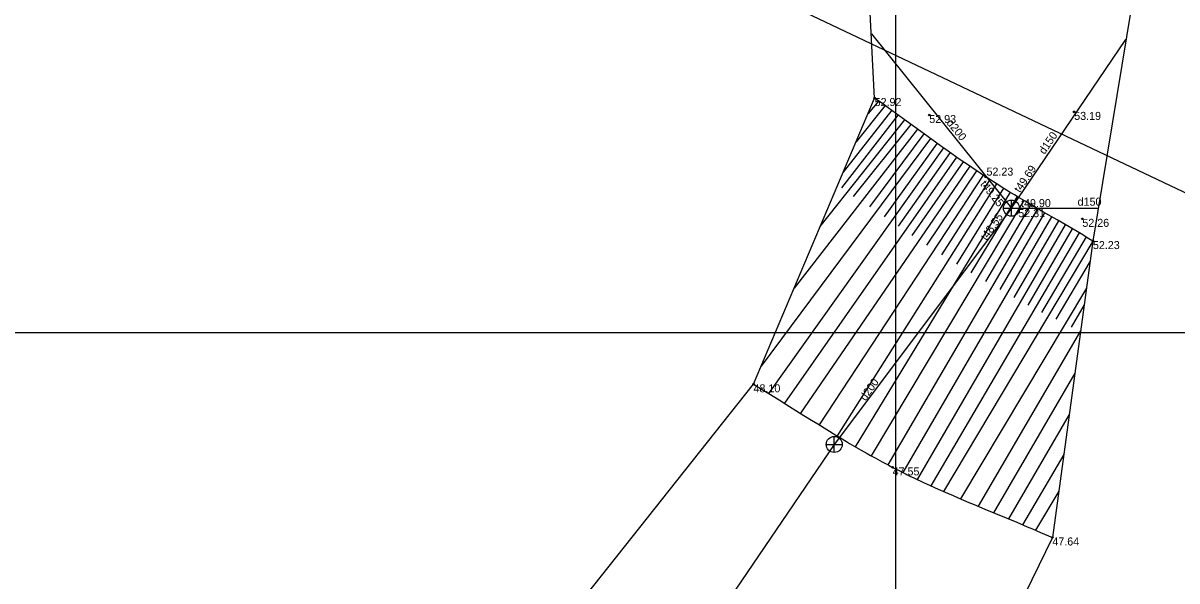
# Model space of a CAD drawing. Extents: x 561134 to 561329, y 413819 to 414116.
# Drawn here: x 561184.1 to 561256.1, y 413952.5 to 413987.3 of the extents above; entities that cross this region are included whole.
import ezdxf

# ---------------------------------------------------------------- set-up
doc = ezdxf.new("R2010")
doc.units = 0
for name, color, linetype in [('RAMI_PLAN_####_TKST_#', 7, 'Continuous'), ('RAMI_UZMR_####_####_#', 7, 'Continuous'), ('RELJ_AATZ_####_TKST_#', 7, 'Continuous'), ('RELJ_ELEM_####_####_#', 7, 'Continuous'), ('RELJ_NOGA_####_####_#', 7, 'Continuous'), ('RELJ_NOGL_####_####_#', 7, 'Continuous'), ('ROBZ_UZMR_####_####_#', 7, 'Continuous'), ('SKAN_ELEM_####_####_#', 7, 'Continuous'), ('SKAN_ELEM_PAST_TKST_#', 7, 'Continuous'), ('SKAN_VADP_PAST_####_#', 7, 'Continuous'), ('SKAN_VADP_PAST_TKST_#', 7, 'Continuous')]:
    doc.layers.add(name, color=color, linetype=linetype)

msp = doc.modelspace()

# ---------------------------------------------------------------- linework, layer by layer
at = {"layer": 'RAMI_PLAN_####_TKST_#'}
for p, q in [((561238.578, 413967.995), (561238.578, 414116.495)), ((561328.578, 413967.995), (561133.578, 413967.995)), ((561238.578, 413819.495), (561238.578, 413967.995))]:
    msp.add_line(p, q, dxfattribs=at)
at = {"layer": 'RAMI_UZMR_####_####_#'}
for points in [[(561188.512, 413892.082), (561185.041, 413910.753), (561191.104, 413917.736), (561189.205, 413920.568), (561187.984, 413924.22), (561187.954, 413928.121), (561192.417, 413932.029), (561202.582, 413934.262), (561206.983, 413936.681), (561215.453, 413945.229), (561216.519, 413946.905), (561218.27, 413950.393), (561229.69, 413964.77), (561237.253, 413982.653), (561235.655, 414013.737)], [(561254.18, 413993.826), (561250.885, 413973.719), (561248.352, 413955.204), (561242.331, 413942.835), (561241.508, 413940.241), (561240.647, 413938.452), (561234.45, 413929.795), (561214.305, 413914.287), (561206.991, 413896.237), (561188.512, 413892.082)]]:
    msp.add_lwpolyline(points, dxfattribs=at)
at = {"layer": 'RELJ_ELEM_####_####_#'}
for centre in [(561237.253, 413982.653), (561249.717, 413981.787), (561240.665, 413981.592), (561244.192, 413977.725), (561250.225, 413975.106), (561250.885, 413973.719), (561229.69, 413964.77), (561238.375, 413959.583), (561248.352, 413955.204)]:
    msp.add_circle(centre, 0.05, dxfattribs=at)
at = {"layer": 'RELJ_NOGA_####_####_#'}
for p, q in [((561237.508, 413982.471), (561236.844, 413981.686)), ((561238.319, 413981.887), (561235.292, 413978.016)), ((561237.914, 413982.18), (561236.094, 413979.912)), ((561233.858, 413974.624), (561239.128, 413981.298)), ((561235.209, 413977.042), (561238.724, 413981.593)), ((561235.938, 413976.5), (561239.532, 413981.004)), ((561239.936, 413980.71), (561232.23, 413970.775)), ((561236.949, 413975.863), (561240.34, 413980.415)), ((561240.745, 413980.122), (561230.169, 413965.903)), ((561241.556, 413979.537), (561230.624, 413964.204)), ((561241.15, 413979.829), (561237.837, 413975.236)), ((561242.372, 413978.959), (561231.622, 413963.588)), ((561241.964, 413979.248), (561238.712, 413974.642)), ((561243.195, 413978.391), (561232.627, 413962.96)), ((561242.783, 413978.674), (561239.582, 413974.056)), ((561243.609, 413978.111), (561240.487, 413973.458)), ((561244.026, 413977.834), (561233.781, 413962.24)), ((561244.445, 413977.561), (561241.422, 413972.856)), ((561244.866, 413977.292), (561234.905, 413961.55)), ((561245.716, 413976.765), (561236.038, 413960.874)), ((561245.29, 413977.027), (561242.356, 413972.275)), ((561246.572, 413976.248), (561237.035, 413960.304)), ((561246.143, 413976.505), (561243.26, 413971.73)), ((561247.002, 413975.994), (561244.17, 413971.199)), ((561247.433, 413975.74), (561238.07, 413959.742)), ((561248.297, 413975.236), (561239.003, 413959.265)), ((561247.865, 413975.488), (561245.072, 413970.688)), ((561249.161, 413974.733), (561239.903, 413958.83)), ((561248.729, 413974.985), (561245.945, 413970.203)), ((561249.593, 413974.481), (561246.823, 413969.722)), ((561250.025, 413974.229), (561240.761, 413958.433)), ((561250.455, 413973.975), (561247.665, 413969.259)), ((561250.885, 413973.719), (561241.553, 413958.079)), ((561250.713, 413972.462), (561248.568, 413968.837)), ((561250.481, 413970.769), (561242.615, 413957.619)), ((561250.341, 413969.745), (561249.517, 413968.351)), ((561250.118, 413968.109), (561243.708, 413957.158)), ((561249.757, 413965.473), (561244.682, 413956.752)), ((561249.402, 413962.878), (561245.611, 413956.367)), ((561249.061, 413960.387), (561246.489, 413956.001)), ((561248.748, 413958.099), (561247.293, 413955.661))]:
    msp.add_line(p, q, dxfattribs=at)
msp.add_lwpolyline([(561250.885, 413973.719), (561250.637, 413973.867), (561250.14, 413974.161), (561249.641, 413974.454), (561248.642, 413975.035), (561247.753, 413975.552), (561247.31, 413975.812), (561246.646, 413976.204), (561246.206, 413976.467), (561245.986, 413976.6), (561245.657, 413976.8), (561245.22, 413977.07), (561245.002, 413977.206), (561244.677, 413977.412), (561244.353, 413977.62), (561244.192, 413977.725), (561243.929, 413977.898), (561243.754, 413978.014), (561243.405, 413978.248), (561243.231, 413978.366), (561242.885, 413978.603), (561242.539, 413978.843), (561242.31, 413979.003), (561241.852, 413979.326), (561241.51, 413979.57), (561241.282, 413979.734), (561240.827, 413980.062), (561240.147, 413980.556), (561239.241, 413981.217), (561238.788, 413981.547), (561238.107, 413982.041), (561237.766, 413982.287), (561237.253, 413982.653)], dxfattribs=at)
at = {"layer": 'RELJ_NOGL_####_####_#'}
msp.add_lwpolyline([(561229.69, 413964.77), (561230.011, 413964.577), (561230.225, 413964.448), (561230.652, 413964.188), (561231.29, 413963.794), (561231.715, 413963.53), (561232.564, 413962.999), (561233.318, 413962.528), (561233.695, 413962.293), (561234.262, 413961.942), (561234.831, 413961.594), (561235.116, 413961.422), (561235.497, 413961.193), (561235.688, 413961.08), (561235.974, 413960.911), (561236.406, 413960.66), (561236.791, 413960.44), (561236.985, 413960.332), (561237.275, 413960.17), (561237.567, 413960.011), (561237.713, 413959.932), (561238.007, 413959.775), (561238.154, 413959.698), (561238.375, 413959.583), (561238.734, 413959.4), (561238.974, 413959.28), (561239.134, 413959.2), (561239.456, 413959.043), (561239.698, 413958.927), (561239.86, 413958.85), (561240.184, 413958.698), (561240.347, 413958.622), (561240.672, 413958.473), (561240.999, 413958.325), (561241.217, 413958.227), (561241.655, 413958.034), (561242.148, 413957.819), (561242.478, 413957.677), (561243.138, 413957.396), (561243.469, 413957.257), (561244.132, 413956.98), (561245.46, 413956.43), (561246.123, 413956.154), (561246.785, 413955.876), (561247.116, 413955.737), (561247.611, 413955.525), (561248.105, 413955.312), (561248.352, 413955.204)], dxfattribs=at)
at = {"layer": 'ROBZ_UZMR_####_####_#'}
msp.add_line((561296.51, 413957.82), (561148.578, 414028.026), dxfattribs=at)
at = {"layer": 'SKAN_ELEM_####_####_#'}
for p, q in [((561245.792, 413975.274), (561245.792, 413976.274)), ((561245.292, 413975.774), (561246.292, 413975.774)), ((561234.729, 413960.518), (561234.729, 413961.518)), ((561234.229, 413961.018), (561235.229, 413961.018))]:
    msp.add_line(p, q, dxfattribs=at)
for centre in [(561245.792, 413975.774), (561234.729, 413961.018)]:
    msp.add_circle(centre, 0.5, dxfattribs=at)
at = {"layer": 'SKAN_VADP_PAST_####_#'}
for p, q in [((561237.046, 413986.67), (561245.792, 413975.774)), ((561245.792, 413975.774), (561252.95, 413986.318)), ((561245.792, 413975.774), (561234.729, 413961.018)), ((561245.792, 413975.774), (561251.222, 413975.778)), ((561234.729, 413961.018), (561215.454, 413932.7))]:
    msp.add_line(p, q, dxfattribs=at)

# ---------------------------------------------------------------- texts
at = {"layer": 'RELJ_AATZ_####_TKST_#'}
for s, p in [('52.92', (561237.253, 413982.153)), ('53.19', (561249.717, 413981.287)), ('52.93', (561240.665, 413981.092)), ('52.23', (561244.238, 413977.807)), ('52.26', (561250.225, 413974.606)), ('52.23', (561250.885, 413973.219)), ('48.10', (561229.69, 413964.27)), ('47.55', (561238.375, 413959.083)), ('47.64', (561248.352, 413954.704))]:
    msp.add_text(s, height=0.5, dxfattribs=at).set_placement(p)
at = {"layer": 'SKAN_ELEM_PAST_TKST_#'}
msp.add_text(' 52.31', height=0.5, dxfattribs=at).set_placement((561246.037, 413975.212))
at = {"layer": 'SKAN_VADP_PAST_TKST_#'}
for s, rotation, p in [('d200', 308.75133, (561241.715, 413981.094)), ('d150', 55.82909, (561247.867, 413979.098)), ('t49.69', 55.82909, (561246.331, 413976.7)), ('t49.25', 308.75133, (561243.815, 413977.26)), ('t49.90', 0.04315, (561246.396, 413975.839)), ('d150', 0.04315, (561249.929, 413975.927)), ('t48.55', 54.84209, (561244.233, 413973.714)), ('d200', 54.84209, (561236.688, 413963.701))]:
    msp.add_text(s, height=0.5, rotation=rotation, dxfattribs=at).set_placement(p)

doc.saveas('drawing.dxf')
